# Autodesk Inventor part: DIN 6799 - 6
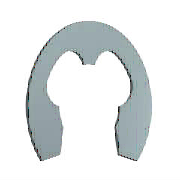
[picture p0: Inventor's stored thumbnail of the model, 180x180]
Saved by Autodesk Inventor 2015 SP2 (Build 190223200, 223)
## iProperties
Created: 2014-02
Part Number: DIN 6799 - 6
Material: Stahl, weich
Description: Sicherungsscheibe
Document SubType Name: Modeling
Standard: DIN 6799
Designer: rYan
Standards Organization: DIN
Language: de-DE
Size Designation: 6
Categories: <MemberInstance><Categories><Category DisplayName="Wellenteile" InternalName="7f7aeb1f-a693-4053-b835-cee3144e0d98" Mnemonic="SHFT"><Category DisplayName="Siche
Density: 7.85 g/cm^3
Appearance: Halbpoliert
IsCustomPart: 0
Author: rYan
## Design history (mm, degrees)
sketch "Skizze1"
  geometry: L1 (-0.6, 0.024)-(0, 0.024) reference; L2 (-3.206, 0)-(3.486, 0) reference; L3 (-2.75, -4.676)-(2.75, -4.676); L4 (0, 1.949)-(0, -3.479) reference; L5 (-3.6, -2.276)-(-3.012, -2.276); L6 (-0.6, 0.124)-(-0.6, 0.706); L7 (0, 2.674)-(2.53, 2.674); L8 (-2.75, -4.676)-(-3.514, -6.72); L9 (0, -0.476)-(-1.278, -0.476); L10 (2.75, -4.676)-(3.514, -6.72); L11 (3.6, -2.276)-(3.012, -2.276); L12 (0.6, 0.124)-(0.6, 0.706); C1 r 3.5 at (0, -3.476); A1 r 3 centre (0, -3.476) between (-2.841, -2.514) and (-2.75, -4.676); A2 r 0.6 centre (0, 0.124) between (-0.6, 0.124) and (0.6, 0.124); A3 r 6.15 centre (0, -3.476) between (5.104, -6.907) and (-5.104, -6.907); A4 r 4.8 centre (0, -3.476) between (-1.2, 1.171) and (-4.235, -1.218); A5 r 0.48 centre (-1.08, 0.706) between (-0.6, 0.706) and (-1.2, 1.171); A6 r 0.72 centre (-3.6, -1.556) between (-4.235, -1.218) and (-3.6, -2.276); A7 r 0.18 centre (-3.012, -2.456) between (-2.841, -2.514) and (-3.012, -2.276); A8 r 0.9 centre (-4.357, -6.405) between (-5.104, -6.907) and (-3.514, -6.72); A9 r 0.9 centre (4.357, -6.405) between (3.514, -6.72) and (5.104, -6.907); A10 r 3 centre (0, -3.476) between (2.75, -4.676) and (2.841, -2.514); A11 r 0.18 centre (3.012, -2.456) between (3.012, -2.276) and (2.841, -2.514); A12 r 0.72 centre (3.6, -1.556) between (3.6, -2.276) and (4.235, -1.218); A13 r 4.8 centre (0, -3.476) between (4.235, -1.218) and (1.2, 1.171); A14 r 0.48 centre (1.08, 0.706) between (1.2, 1.171) and (0.6, 0.706); 1 further point
  constraints: 30 point on circle, 20 end point, 15 centre point, 13 symmetric about line, 12 tangent, 8 point on line, 4 parallel, 2 coincident, 2 horizontal, 1 concentric, 1 perpendicular, 1 vertical alignment, 9 other
  dimensions: "d0" = 7 diameter of C1 (= WD); "d3" = 1.2 distance from line of A1.centre L3 (= 0.2 x ND); "d4" = 0.6 radius of A2 (= 0.1 x ND); "d5" = 12.3 diameter of A3 (= SD2); "d8" = 4.8 radius of A4 (= 0.8 x ND); "d9" = 1.2 distance from line of A1.centre L5 (= 0.2 x ND); "d10" = 0.48 radius of A5 (= 0.08 x ND); "d11" = 0.72 radius of A6 (= 0.12 x ND); "d12" = 0.18 radius of A7 (= 0.03 x ND); "d13" = 0.9 radius of A8 (= 0.15 x ND); "d14" = 3 distance from line of A1.centre L9 (= 0.5 x ND); "d15" = 3 radius of A1 (= 0.5 x ND)
extrude "Körper" new body sketch "Skizze1" distance "d16" = 0.7 (= SD); taper "d17" = 0 deg
workaxis "Work Axis1"
workaxis "Work Axis2"
workplane "Work Plane1"
body "Solid1"
other parameters: "ND" = 6 [user parameter; used in 14 equation terms], "SD" = 0.7 [user parameter; used in 1 equation term], "WD" = 7 [user parameter; used in 1 equation term], "d1" = 9.6 (= 1.6 x ND), "d2" = 6 (= ND), "SD2" = 12.3 [user parameter; used in 1 equation term], "d6" = 6 (= ND), "d7" = 0.9 (= 0.15 x ND), "d18" = 0, "d19" = 0, "d27" = 0, "d28" = 0, "WDMIN" = 6 [user parameter], "SNB" = 0.74 [user parameter], "WDMAX" = 8 [user parameter], "BUBRMI" = 1.2 [user parameter]
